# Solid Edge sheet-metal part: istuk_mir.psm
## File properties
Author: Argu
Template: Iso Sheet Metal.psm
Last saved by: Argu
Revision: 4
Application: Solid Edge
Accuracy: 0,990
Material Thickness: 0,10 mm
Bend Radius: 1,00 mm
Relief Width: 1,00 mm
Relief Length: 0,00 mm
Neutral Factor: 0,330
Minimum Arc Length: 0,10 mm
Deviational Tolerance: 0,10 mm
Username: Argu
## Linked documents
istuk.psm
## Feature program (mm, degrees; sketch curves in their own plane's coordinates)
part copy "CopiedPart_1"
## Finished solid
Body 1: solid body, 122 faces, 278 edges, 165 vertices.
  Faces by surface: plane 51, cylinder 29, torus 18, cone 16, sphere 4, spline 4
  Edges by curve: line 150, circle 118, curve on surface 8, intersection 2
Bounding box of the edges (mm; curved faces can reach further): 43.735 x 29.999 x 39.023, from (-18.6054, -14.9996, 2.4208) to (25.1301, 14.9996, 41.4439).
Cylindrical faces by radius (mm): R0.1 x16, R1 x4, R1.1 x4, R2.4625 x1, R2.5625 x1, R5.2029 x1, R5.3029 x1, R10 x1
Conical faces (half-angle, radius in mm at the cone's reference point): 15 deg R0.0301 x4, 15 deg R0.0636 x4, 15 deg R0.1267 x4, 15 deg R0.1602 x4
Toroidal faces (ring radius, tube radius in mm): R0.05 r0.1 x8, R0.1602 r0.1 x8, R6.3029 r1 x1, R6.3029 r1.1 x1
Spherical faces by radius (mm): R2.4625 x2, R2.5625 x2
Planar faces by outward normal: oblique 51
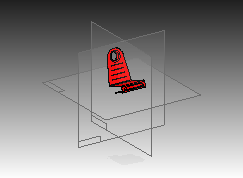
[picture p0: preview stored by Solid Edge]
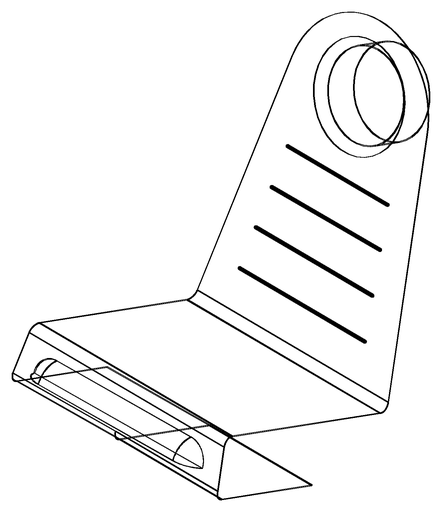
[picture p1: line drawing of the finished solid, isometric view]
